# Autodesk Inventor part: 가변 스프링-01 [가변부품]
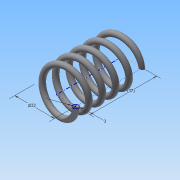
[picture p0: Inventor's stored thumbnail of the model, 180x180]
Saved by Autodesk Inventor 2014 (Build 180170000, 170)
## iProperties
Created: 2015-09
Part Number: 가변 스프링-01 [가변부품]
Material: 강철, 탄소
Document SubType Name: Modeling
Designer: study
Density: 7.87 g/cm^3
Appearance: 반연마
Mass: 18.9204 g
Surface Area: 32.5878 cm^2
Volume: 2.40412 cm^3
Author: study
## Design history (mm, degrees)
sketch "스케치1"
  geometry: L1 (0, 0)-(11, 0); L2 (11, 0)-(11, 40.761); L3 (11, 40.761)-(0, 40.761); L4 (0, 40.761)-(0, 0); C1 r 1.5 at (11, 0)
  constraints: 8 end point, 2 parallel, 1 centre point, 1 coincident, 1 horizontal, 1 perpendicular
  dimensions: "d0" = 22 diameter of L2 L4; "d1" = 3 diameter of C1; "d2" = 40.7612 distance between parallel lines of L3 L1 (derived)
feature "코일1" sketch "스케치1" pitch "d3" = 10; turns "d5" = 5; dims "d4" = 40.7612 (= d2), "d6" = 0, angle "d7" = 90 deg, angle "d8" = 90 deg, "d9" = 0, "d10" = 0
node "작업 평면1"
sketch "스케치2"
  geometry: L1 (-12.5, 0)-(-9.5, 0) reference; 1 further point
  constraints: 1 horizontal alignment
extrude "돌출1" cut sketch "스케치2" stored distance "d12" = 10; taper "d13" = 0 deg
node "작업 평면2"
sketch "스케치3"
  geometry: L1 (-9.5, 0)-(-12.5, 0) reference; L2 (-9.5, 0)-(-12.5, 0) reference; 1 further point
  constraints: 2 horizontal alignment
extrude "돌출2" cut sketch "스케치3" stored distance "d15" = 10; taper "d16" = 0 deg
node "솔리드1"
node "절단 모서리 투영1"
node "절단 모서리 투영2"
node "절단 모서리 투영3"
other parameters: "d11" = 0, "d14" = 40.7612 (= d2)
